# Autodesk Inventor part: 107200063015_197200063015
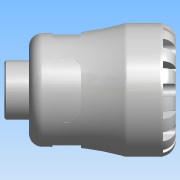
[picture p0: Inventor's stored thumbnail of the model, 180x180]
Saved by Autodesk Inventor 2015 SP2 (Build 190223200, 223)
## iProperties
Created: 2016-12
Part Number: 107200063015_197200063015
Material: PVC-Piping
Description: PLASSON MALE INTEGRAL BRASS THREAD 63X1.1/2" SERIES 1
Document SubType Name: Modeling
Designer: KIM
Mass: 61.7504 g
Surface Area: 140.097 cm^2
Volume: 44.1074 cm^3
Density: 1.4 g/cm^3
Appearance: Smooth - White
Author: KIM
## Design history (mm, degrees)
derived "1072.ipt"
feature "Solid1::1072.ipt"
tag "TaggingFeature1"
body "Solid1"
other parameters: "d0" = 132, "d1" = 38.64, "d2" = 63, "d3" = 78.75, "d4" = 103, "d6" = 92, "d8" = 87.55, "d13" = 9.7, "d14" = 9.7, "d15" = 0, "d17" = 360 deg, "d19" = 8 deg, "d20" = 1.26, "d21" = 1.26, "d22" = 8 deg, "d24" = 0, "d26" = 360 deg, "d32" = 10.3, "d33" = 10.3, "d34" = 45.485, "d38" = 19, "d39" = 1.36455, "d42" = 22.05, "d43" = 14.49, "d45" = 19.012, "d46" = 0, "d59" = 360 deg, "d61" = 18.7425, "d62" = 1.26, "d64" = 0, "d65" = 1.03, "d68" = 9, "d_" = 63, "E_" = 103, "H_" = 132, "l_" = 92, "R_" = 45.485, "l_2" = 19, "d9" = 12.125, "d11" = 103, "d12" = 78.75
